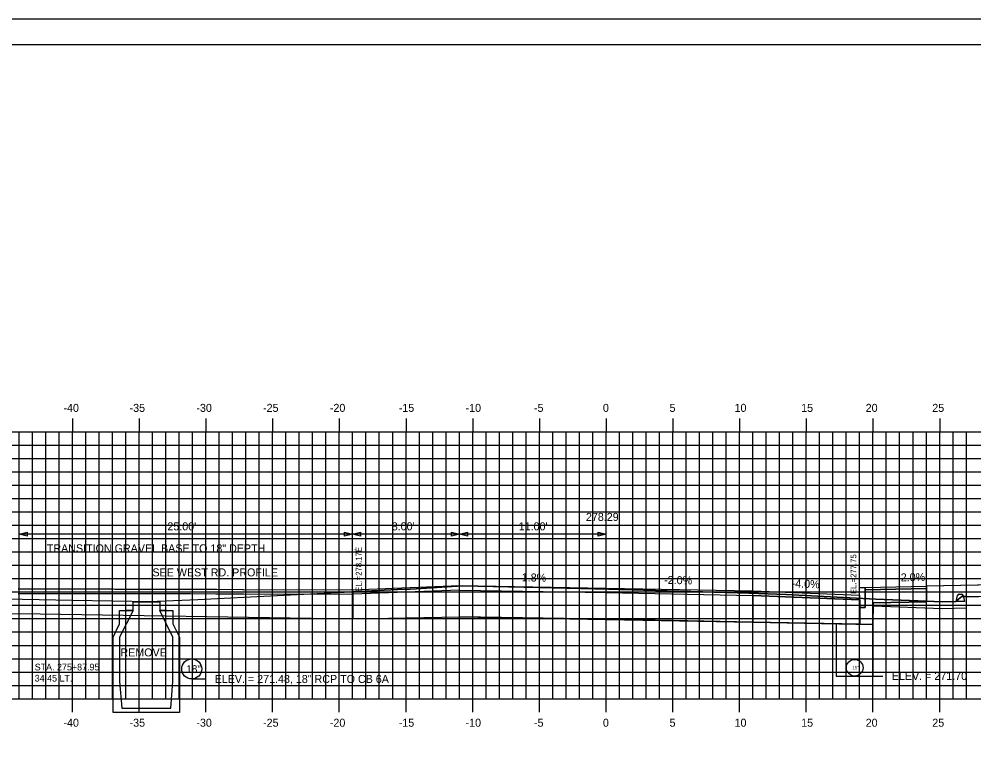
# Model space of a CAD drawing. Extents: x 853563 to 853733, y 366268 to 366378.
# Drawn here: x 853601.8 to 853673.3, y 366324.1 to 366378.2 of the extents above; entities that cross this region are included whole.
import ezdxf

# ---------------------------------------------------------------- set-up
doc = ezdxf.new("R2010")
doc.units = 0
for name, color, linetype in [('ANNOTATION', 7, 'Continuous'), ('BORDER', 7, 'Continuous'), ('D_Curb_Type_1_Rt', 7, 'Continuous'), ('D_Drainage_Culvert', 7, 'Continuous'), ('D_Roadway_Centerline_Text', 7, 'Continuous'), ('D_Roadway_Edge_Shoulder', 7, 'Continuous'), ('D_Roadway_Edge_TW', 7, 'Continuous'), ('D_Roadway_FinishedGrade', 7, 'Continuous'), ('D_Roadway_Sidewalks_Paved', 7, 'Continuous'), ('D_Roadway_SubGrade', 7, 'Continuous'), ('D_Text_Monospaced', 7, 'Continuous'), ('D_Text_Standard', 7, 'Continuous'), ('DIMENSIONS', 7, 'Continuous'), ('H_V ANNOTATION', 7, 'Continuous'), ('JUNK COM EXC', 7, 'Continuous'), ('JUNK FILL', 7, 'Continuous'), ('junk grubnfill', 7, 'Continuous'), ('junk strct exc', 7, 'Continuous'), ('MAJOR', 7, 'Continuous'), ('MINOR', 7, 'Continuous'), ('PDRAIN', 7, 'Continuous'), ('PLOT BOUNDARY', 7, 'Continuous'), ('S_Curb_Type_3', 7, 'Continuous'), ('S_Drainage_CB', 7, 'Continuous'), ('S_Roadway_Centerline', 7, 'Continuous')]:
    doc.layers.add(name, color=color, linetype=linetype)

msp = doc.modelspace()

# ---------------------------------------------------------------- linework, layer by layer
at = {"layer": 'BORDER'}
msp.add_line((853730.768, 366376.236), (853570.768, 366376.236), dxfattribs=at)
at = {"layer": 'D_Curb_Type_1_Rt'}
for points in [[(853665.184, 366335.573), (853665.184, 366334.073), (853664.767, 366334.073), (853664.767, 366335.573)], [(853665.184, 366335.573), (853665.184, 366334.073), (853664.768, 366334.073), (853664.768, 366335.573)]]:
    msp.add_lwpolyline(points, close=True, dxfattribs=at)
at = {"layer": 'D_Drainage_Culvert'}
msp.add_circle((853614.705, 366329.466), 0.75, dxfattribs=at)
at = {"layer": 'D_Roadway_Edge_Shoulder'}
msp.add_lwpolyline([(853656.768, 366335.31), (853664.768, 366334.99), (853664.768, 366334.656), (853656.768, 366334.976)], close=True, dxfattribs=at)
at = {"layer": 'D_Roadway_Edge_TW'}
msp.add_line((853626.768, 366335.393), (853626.771, 366335.06), dxfattribs=at)
for points in [[(853626.768, 366335.393), (853634.768, 366335.713), (853645.768, 366335.53), (853656.768, 366335.31), (853664.767, 366334.989)], [(853601.69, 366335.461), (853601.808, 366335.46), (853601.92, 366335.461), (853601.952, 366335.461), (853602.205, 366335.461), (853602.274, 366335.461), (853602.357, 366335.461), (853602.379, 366335.461), (853603.085, 366335.461), (853603.249, 366335.461), (853603.378, 366335.461), (853603.406, 366335.461), (853604.083, 366335.462), (853604.326, 366335.462), (853604.455, 366335.462), (853604.748, 366335.462), (853605.038, 366335.462), (853605.079, 366335.462), (853605.128, 366335.462), (853605.968, 366335.462), (853606.01, 366335.462), (853606.13, 366335.462), (853606.421, 366335.462), (853606.531, 366335.462), (853606.973, 366335.461), (853606.987, 366335.461), (853607.53, 366335.461), (853607.562, 366335.461), (853607.882, 366335.461), (853607.927, 366335.461), (853608.509, 366335.46), (853608.558, 366335.46), (853608.848, 366335.46), (853608.953, 366335.459), (853608.98, 366335.459), (853610.291, 366335.457), (853610.332, 366335.457), (853610.549, 366335.456), (853610.569, 366335.456), (853610.576, 366335.456), (853611.676, 366335.453), (853611.753, 366335.454), (853612.585, 366335.451), (853613.067, 366335.449), (853613.079, 366335.449), (853614.523, 366335.443), (853614.584, 366335.443), (853616.515, 366335.436), (853616.561, 366335.436), (853616.586, 366335.436), (853618.522, 366335.429), (853618.578, 366335.429), (853626.768, 366335.393)], [(853601.69, 366335.128), (853601.808, 366335.127), (853601.92, 366335.128), (853601.951, 366335.128), (853602.205, 366335.128), (853602.274, 366335.128), (853602.357, 366335.128), (853602.379, 366335.128), (853603.085, 366335.128), (853603.249, 366335.128), (853603.378, 366335.128), (853603.406, 366335.128), (853604.083, 366335.129), (853604.326, 366335.129), (853604.455, 366335.129), (853604.748, 366335.129), (853605.038, 366335.129), (853605.079, 366335.129), (853605.968, 366335.129), (853606.01, 366335.129), (853606.13, 366335.129), (853606.421, 366335.129), (853606.531, 366335.129), (853606.973, 366335.128), (853606.987, 366335.128), (853607.53, 366335.128), (853607.562, 366335.128), (853607.882, 366335.128), (853607.927, 366335.128), (853608.509, 366335.127), (853608.558, 366335.127), (853608.848, 366335.127), (853608.953, 366335.126), (853608.98, 366335.126), (853610.291, 366335.124), (853610.332, 366335.124), (853610.549, 366335.123), (853610.569, 366335.123), (853610.575, 366335.123), (853611.676, 366335.12), (853611.753, 366335.121), (853612.584, 366335.118), (853613.067, 366335.116), (853613.079, 366335.116), (853614.523, 366335.11), (853614.584, 366335.11), (853616.515, 366335.103), (853616.561, 366335.103), (853616.585, 366335.103), (853618.522, 366335.096), (853618.578, 366335.096), (853626.771, 366335.06)]]:
    msp.add_lwpolyline(points, dxfattribs=at)
at = {"layer": 'D_Roadway_FinishedGrade'}
msp.add_line((853685.017, 366335.97), (853669.773, 366335.664), dxfattribs=at)
at = {"layer": 'D_Roadway_Sidewalks_Paved'}
for points in [[(853665.184, 366335.573), (853669.773, 366335.665), (853669.773, 366335.498), (853665.184, 366335.406)], [(853665.184, 366335.572), (853669.773, 366335.664), (853669.773, 366335.497), (853665.184, 366335.406)]]:
    msp.add_lwpolyline(points, close=True, dxfattribs=at)
at = {"layer": 'D_Roadway_SubGrade'}
for p, q in [((853601.768, 366333.627), (853601.768, 366335.127)), ((853672.768, 366334.037), (853672.768, 366334.9))]:
    msp.add_line(p, q, dxfattribs=at)
for points in [[(853634.771, 366335.38), (853626.771, 366335.06), (853626.771, 366333.22), (853634.771, 366333.38)], [(853634.771, 366333.38), (853634.771, 366335.38), (853645.771, 366335.196), (853656.771, 366334.976), (853656.771, 366332.976), (853645.771, 366333.196)], [(853656.768, 366334.976), (853664.768, 366334.656), (853664.768, 366334.073), (853664.768, 366332.816), (853656.768, 366332.976)], [(853656.771, 366334.976), (853664.771, 366334.656), (853664.771, 366332.816), (853656.771, 366332.976)], [(853665.184, 366335.406), (853669.773, 366335.498), (853669.773, 366334.498), (853665.773, 366334.418), (853665.768, 366332.796), (853664.768, 366332.816), (853664.768, 366334.073), (853665.184, 366334.073)]]:
    msp.add_lwpolyline(points, close=True, dxfattribs=at)
for points in [[(853664.771, 366332.816), (853665.771, 366332.796), (853665.771, 366334.418), (853669.773, 366334.497), (853669.773, 366335.497)], [(853665.771, 366334.207), (853670.96, 366333.998), (853672.768, 366334.037)], [(853576.803, 366333.458), (853601.768, 366333.627), (853626.771, 366333.22)]]:
    msp.add_lwpolyline(points, dxfattribs=at)
at = {"layer": 'D_Text_Standard'}
for points in [[(853614.705, 366328.716), (853615.063, 366328.716), (853615.743, 366328.716)], [(853665.771, 366328.936), (853665.817, 366328.936), (853666.497, 366328.936)]]:
    msp.add_lwpolyline(points, dxfattribs=at)
at = {"layer": 'DIMENSIONS'}
for p, q in [((853601.768, 366335.845), (853601.768, 366339.957)), ((853626.768, 366335.593), (853626.768, 366339.957)), ((853626.768, 366336.884), (853626.768, 366339.957)), ((853634.768, 366335.913), (853634.768, 366339.957)), ((853645.768, 366335.73), (853645.768, 366339.957)), ((853626.768, 366339.557), (853601.768, 366339.557)), ((853634.768, 366339.557), (853626.768, 366339.557)), ((853645.768, 366339.557), (853634.768, 366339.557))]:
    msp.add_line(p, q, dxfattribs=at)
for points in [[(853602.368, 366339.407), (853601.768, 366339.557), (853602.368, 366339.707)], [(853626.168, 366339.707), (853626.768, 366339.557), (853626.168, 366339.407)], [(853627.368, 366339.407), (853626.768, 366339.557), (853627.368, 366339.707)], [(853634.168, 366339.707), (853634.768, 366339.557), (853634.168, 366339.407)], [(853635.368, 366339.407), (853634.768, 366339.557), (853635.368, 366339.707)], [(853645.168, 366339.707), (853645.768, 366339.557), (853645.168, 366339.407)]]:
    msp.add_lwpolyline(points, close=True, dxfattribs=at)
at = {"layer": 'JUNK COM EXC'}
msp.add_lwpolyline([(853626.768, 366335.249), (853626.771, 366333.22), (853634.771, 366333.38), (853656.771, 366332.976), (853665.771, 366332.796), (853665.771, 366334.418), (853669.773, 366334.497), (853669.773, 366334.546), (853665.98, 366334.699), (853662.578, 366334.881), (853659.261, 366335.059), (853656.49, 366335.136), (853645.97, 366335.444), (853640.757, 366335.567), (853635.009, 366335.685), (853631.517, 366335.478), (853631.077, 366335.457), (853630.126, 366335.415), (853626.768, 366335.249)], dxfattribs=at)
at = {"layer": 'JUNK FILL'}
msp.add_lwpolyline([(853669.768, 366335.664), (853669.768, 366335.497), (853669.773, 366335.497), (853669.773, 366334.546), (853669.775, 366334.546), (853670.965, 366334.498), (853671.996, 366334.52), (853672.426, 366334.897), (853672.831, 366334.9), (853673.692, 366334.906), (853676.746, 366334.989), (853679.799, 366335.073), (853681.402, 366335.295), (853683.005, 366335.518), (853685.081, 366335.984), (853677.395, 366335.817), (853669.773, 366335.664)], close=True, dxfattribs=at)
at = {"layer": 'junk grubnfill'}
msp.add_lwpolyline([(853669.773, 366334.546), (853669.773, 366334.497), (853665.771, 366334.418), (853665.771, 366334.207), (853670.96, 366333.998), (853672.768, 366334.037), (853672.768, 366334.9), (853672.426, 366334.897), (853672.062, 366334.59), (853671.996, 366334.52), (853670.965, 366334.498), (853669.773, 366334.546)], dxfattribs=at)
at = {"layer": 'junk strct exc'}
msp.add_lwpolyline([(853663.021, 366332.851), (853663.021, 366328.936), (853665.771, 366328.936), (853665.771, 366332.796)], close=True, dxfattribs=at)
at = {"layer": 'MAJOR'}
for p, q in [((853605.768, 366348.238), (853605.768, 366347.236)), ((853610.768, 366348.238), (853610.768, 366347.236)), ((853615.768, 366348.238), (853615.768, 366347.236)), ((853620.768, 366348.238), (853620.768, 366347.236)), ((853625.768, 366348.238), (853625.768, 366347.236)), ((853630.768, 366348.238), (853630.768, 366347.236)), ((853635.768, 366348.238), (853635.768, 366347.236)), ((853640.768, 366348.238), (853640.768, 366347.236)), ((853645.768, 366348.238), (853645.768, 366347.236)), ((853650.768, 366348.238), (853650.768, 366347.236)), ((853655.768, 366348.238), (853655.768, 366347.236)), ((853660.768, 366348.238), (853660.768, 366347.236)), ((853665.768, 366348.238), (853665.768, 366347.236)), ((853670.768, 366348.238), (853670.768, 366347.236)), ((853575.768, 366347.236), (853715.768, 366347.236)), ((853575.768, 366347.236), (853715.768, 366347.236)), ((853605.768, 366327.236), (853605.768, 366347.236)), ((853610.768, 366327.236), (853610.768, 366347.236)), ((853615.768, 366327.236), (853615.768, 366347.236)), ((853620.768, 366327.236), (853620.768, 366347.236)), ((853625.768, 366327.236), (853625.768, 366347.236)), ((853630.768, 366327.236), (853630.768, 366347.236)), ((853635.768, 366327.236), (853635.768, 366347.236)), ((853640.768, 366327.236), (853640.768, 366347.236)), ((853645.768, 366327.236), (853645.768, 366347.236)), ((853650.768, 366327.236), (853650.768, 366347.236)), ((853655.768, 366327.236), (853655.768, 366347.236)), ((853660.768, 366327.236), (853660.768, 366347.236)), ((853665.768, 366327.236), (853665.768, 366347.236)), ((853670.768, 366327.236), (853670.768, 366347.236)), ((853575.768, 366342.236), (853715.768, 366342.236)), ((853575.768, 366337.236), (853715.768, 366337.236)), ((853575.768, 366332.236), (853715.768, 366332.236)), ((853575.768, 366327.236), (853715.768, 366327.236)), ((853575.768, 366327.236), (853715.768, 366327.236)), ((853605.768, 366326.234), (853605.768, 366327.236)), ((853610.768, 366326.234), (853610.768, 366327.236)), ((853615.768, 366326.234), (853615.768, 366327.236)), ((853620.768, 366326.234), (853620.768, 366327.236)), ((853625.768, 366326.234), (853625.768, 366327.236)), ((853630.768, 366326.234), (853630.768, 366327.236)), ((853635.768, 366326.234), (853635.768, 366327.236)), ((853640.768, 366326.234), (853640.768, 366327.236)), ((853645.768, 366326.234), (853645.768, 366327.236)), ((853650.768, 366326.234), (853650.768, 366327.236)), ((853655.768, 366326.234), (853655.768, 366327.236)), ((853660.768, 366326.234), (853660.768, 366327.236)), ((853665.768, 366326.234), (853665.768, 366327.236)), ((853670.768, 366326.234), (853670.768, 366327.236))]:
    msp.add_line(p, q, dxfattribs=at)
at = {"layer": 'MINOR'}
for p, q in [((853601.768, 366327.236), (853601.768, 366347.236)), ((853602.768, 366327.236), (853602.768, 366347.236)), ((853603.768, 366327.236), (853603.768, 366347.236)), ((853604.768, 366327.236), (853604.768, 366347.236)), ((853606.768, 366327.236), (853606.768, 366347.236)), ((853607.768, 366327.236), (853607.768, 366347.236)), ((853608.768, 366327.236), (853608.768, 366347.236)), ((853609.768, 366327.236), (853609.768, 366347.236)), ((853611.768, 366327.236), (853611.768, 366347.236)), ((853612.768, 366327.236), (853612.768, 366347.236)), ((853613.768, 366327.236), (853613.768, 366347.236)), ((853614.768, 366327.236), (853614.768, 366347.236)), ((853616.768, 366327.236), (853616.768, 366347.236)), ((853617.768, 366327.236), (853617.768, 366347.236)), ((853618.768, 366327.236), (853618.768, 366347.236)), ((853619.768, 366327.236), (853619.768, 366347.236)), ((853621.768, 366327.236), (853621.768, 366347.236)), ((853622.768, 366327.236), (853622.768, 366347.236)), ((853623.768, 366327.236), (853623.768, 366347.236)), ((853624.768, 366327.236), (853624.768, 366347.236)), ((853626.768, 366327.236), (853626.768, 366347.236)), ((853627.768, 366327.236), (853627.768, 366347.236)), ((853628.768, 366327.236), (853628.768, 366347.236)), ((853629.768, 366327.236), (853629.768, 366347.236)), ((853631.768, 366327.236), (853631.768, 366347.236)), ((853632.768, 366327.236), (853632.768, 366347.236)), ((853633.768, 366327.236), (853633.768, 366347.236)), ((853634.768, 366327.236), (853634.768, 366347.236)), ((853636.768, 366327.236), (853636.768, 366347.236)), ((853637.768, 366327.236), (853637.768, 366347.236)), ((853638.768, 366327.236), (853638.768, 366347.236)), ((853639.768, 366327.236), (853639.768, 366347.236)), ((853641.768, 366327.236), (853641.768, 366347.236)), ((853642.768, 366327.236), (853642.768, 366347.236)), ((853643.768, 366327.236), (853643.768, 366347.236)), ((853644.768, 366327.236), (853644.768, 366347.236)), ((853646.768, 366327.236), (853646.768, 366347.236)), ((853647.768, 366327.236), (853647.768, 366347.236)), ((853648.768, 366327.236), (853648.768, 366347.236)), ((853649.768, 366327.236), (853649.768, 366347.236)), ((853651.768, 366327.236), (853651.768, 366347.236)), ((853652.768, 366327.236), (853652.768, 366347.236)), ((853653.768, 366327.236), (853653.768, 366347.236)), ((853654.768, 366327.236), (853654.768, 366347.236)), ((853656.768, 366327.236), (853656.768, 366347.236)), ((853657.768, 366327.236), (853657.768, 366347.236)), ((853658.768, 366327.236), (853658.768, 366347.236)), ((853659.768, 366327.236), (853659.768, 366347.236)), ((853661.768, 366327.236), (853661.768, 366347.236)), ((853662.768, 366327.236), (853662.768, 366347.236)), ((853663.768, 366327.236), (853663.768, 366347.236)), ((853664.768, 366327.236), (853664.768, 366347.236)), ((853666.768, 366327.236), (853666.768, 366347.236)), ((853667.768, 366327.236), (853667.768, 366347.236)), ((853668.768, 366327.236), (853668.768, 366347.236)), ((853669.768, 366327.236), (853669.768, 366347.236)), ((853671.768, 366327.236), (853671.768, 366347.236)), ((853672.768, 366327.236), (853672.768, 366347.236)), ((853575.768, 366346.236), (853715.768, 366346.236)), ((853575.768, 366345.236), (853715.768, 366345.236)), ((853575.768, 366344.236), (853715.768, 366344.236)), ((853575.768, 366343.236), (853715.768, 366343.236)), ((853575.768, 366341.236), (853715.768, 366341.236)), ((853575.768, 366340.236), (853715.768, 366340.236)), ((853575.768, 366339.236), (853715.768, 366339.236)), ((853575.768, 366338.236), (853715.768, 366338.236)), ((853575.768, 366336.236), (853715.768, 366336.236)), ((853575.768, 366335.236), (853715.768, 366335.236)), ((853575.768, 366334.236), (853715.768, 366334.236)), ((853575.768, 366333.236), (853715.768, 366333.236)), ((853575.768, 366331.236), (853715.768, 366331.236)), ((853575.768, 366330.236), (853715.768, 366330.236)), ((853575.768, 366329.236), (853715.768, 366329.236)), ((853575.768, 366328.236), (853715.768, 366328.236))]:
    msp.add_line(p, q, dxfattribs=at)
at = {"layer": 'PDRAIN'}
msp.add_lwpolyline([(853663.021, 366332.851), (853663.021, 366328.936), (853665.771, 366328.936), (853665.771, 366332.796)], dxfattribs=at)
msp.add_circle((853664.396, 366329.561), 0.625, dxfattribs=at)
at = {"layer": 'PLOT BOUNDARY'}
msp.add_lwpolyline([(853562.674, 366268.177), (853732.674, 366268.177), (853732.674, 366378.177), (853562.674, 366378.177)], close=True, dxfattribs=at)
at = {"layer": 'S_Curb_Type_3'}
for points in [[(853672.518, 366334.965), (853672.621, 366334.52), (853671.996, 366334.52), (853672.098, 366334.965)], [(853672.22, 366335.062), (853672.396, 366335.062)]]:
    msp.add_lwpolyline(points, dxfattribs=at)
for centre, start, end in [((853672.22, 366334.937), 90, 167.00538), ((853672.396, 366334.937), 12.99462, 90)]:
    msp.add_arc(centre, 0.125, start, end, dxfattribs=at)
at = {"layer": 'S_Drainage_CB'}
for p, q in [((853609.3, 366332.858), (853609.3, 366333.843)), ((853609.3, 366333.843), (853610.317, 366333.843)), ((853610.317, 366333.843), (853609.3, 366331.841)), ((853612.318, 366333.843), (853613.302, 366333.843)), ((853613.302, 366331.841), (853612.318, 366333.843)), ((853613.302, 366333.843), (853613.302, 366332.858)), ((853608.808, 366331.841), (853609.3, 366332.858)), ((853613.302, 366332.858), (853613.795, 366331.841)), ((853608.808, 366326.198), (853608.808, 366331.841)), ((853609.3, 366331.841), (853609.3, 366328.528)), ((853613.302, 366328.528), (853613.302, 366331.841)), ((853613.795, 366331.841), (853613.795, 366326.198)), ((853609.3, 366328.528), (853609.464, 366326.526)), ((853613.138, 366326.526), (853613.302, 366328.528)), ((853609.464, 366326.526), (853613.138, 366326.526)), ((853613.795, 366326.198), (853608.808, 366326.198))]:
    msp.add_line(p, q, dxfattribs=at)
msp.add_lwpolyline([(853609.825, 366333.884), (853610.317, 366333.884), (853610.317, 366334.508), (853612.318, 366334.508), (853612.318, 366333.884), (853612.81, 366333.884)], dxfattribs=at)
at = {"layer": 'S_Roadway_Centerline'}
msp.add_lwpolyline([(853590.768, 366334.911), (853605.767, 366334.615), (853611.714, 366334.524), (853611.768, 366334.524), (853611.809, 366334.524), (853611.898, 366334.526), (853612.008, 366334.531), (853612.064, 366334.534), (853612.146, 366334.539), (853615.174, 366334.667), (853619.112, 366334.87), (853630.126, 366335.415), (853631.077, 366335.457), (853631.517, 366335.478), (853635.009, 366335.685), (853640.757, 366335.567), (853645.97, 366335.444), (853656.49, 366335.136), (853659.261, 366335.059), (853662.578, 366334.881), (853665.98, 366334.699), (853670.965, 366334.498), (853671.996, 366334.52), (853672.062, 366334.59), (853672.426, 366334.897), (853673.692, 366334.906)], dxfattribs=at)

# ---------------------------------------------------------------- texts
at = {"layer": 'ANNOTATION'}
for s, p in [('TRANSITION GRAVEL BASE TO 18" DEPTH', (853603.846, 366338.207)), ('SEE WEST RD. PROFILE', (853611.764, 366336.404)), ('REMOVE', (853609.363, 366330.408))]:
    msp.add_text(s, height=0.6, dxfattribs=at).set_placement(p)
for s, rotation, p in [('1.8%', 359.04499, (853639.439, 366336.035)), ('-2.0%', 358.85424, (853650.111, 366335.843)), ('2.0%', 1.1478, (853667.855, 366336.026)), ('-4.0%', 357.70939, (853659.663, 366335.595)), ('-4.0%', 357.70925, (853659.663, 366335.594))]:
    msp.add_text(s, height=0.6, rotation=rotation, dxfattribs=at).set_placement(p)
at = {"layer": 'D_Roadway_Centerline_Text'}
msp.add_text('278.29', height=0.6, dxfattribs=at).set_placement((853644.253, 366340.562))
msp.add_text('278.29', height=0.6, dxfattribs=at).set_placement((853644.253, 366340.562))
at = {"layer": 'D_Text_Monospaced'}
for s, height, p in [('STA. 275+87.95', 0.49998, (853602.938, 366329.356)), ('34.45 LT.', 0.5, (853602.938, 366328.522))]:
    msp.add_text(s, height=height, dxfattribs=at).set_placement(p)
at = {"layer": 'D_Text_Standard'}
for s, p in [(' EL.=278.17È', (853627.437, 366335.078)), (' EL.=277.75', (853664.522, 366334.921))]:
    msp.add_text(s, height=0.4335, rotation=90, dxfattribs=at).set_placement(p)
for s, p in [('ELEV. = 271.70', (853667.177, 366328.636)), ('ELEV. = 271.48, 18" RCP TO CB 6A', (853616.423, 366328.416))]:
    msp.add_text(s, height=0.6, dxfattribs=at).set_placement(p)
at = {"layer": 'DIMENSIONS'}
for s, p in [("25.00'", (853612.884, 366339.857)), ("8.00'", (853629.7, 366339.857)), ("11.00'", (853639.216, 366339.857))]:
    msp.add_text(s, height=0.6, dxfattribs=at).set_placement(p)
at = {"layer": 'H_V ANNOTATION'}
for s, p in [('-40', (853605.093, 366348.736)), ('-35', (853610.048, 366348.736)), ('-30', (853615.056, 366348.736)), ('-25', (853620.053, 366348.736)), ('-20', (853625.061, 366348.736)), ('-15', (853630.224, 366348.736)), ('-10', (853635.232, 366348.736)), ('-5', (853640.358, 366348.736)), ('0', (853645.527, 366348.736)), ('5', (853650.519, 366348.736)), ('10', (853655.393, 366348.736)), ('15', (853660.385, 366348.736)), ('20', (853665.222, 366348.736)), ('25', (853670.213, 366348.736)), ('-40', (853605.093, 366325.136)), ('-35', (853610.048, 366325.136)), ('-30', (853615.056, 366325.136)), ('-25', (853620.053, 366325.136)), ('-20', (853625.061, 366325.136)), ('-15', (853630.224, 366325.136)), ('-10', (853635.232, 366325.136)), ('-5', (853640.358, 366325.136)), ('0', (853645.527, 366325.136)), ('5', (853650.519, 366325.136)), ('10', (853655.393, 366325.136)), ('15', (853660.385, 366325.136)), ('20', (853665.222, 366325.136)), ('25', (853670.213, 366325.136))]:
    msp.add_text(s, height=0.6, dxfattribs=at).set_placement(p)
at = {"layer": 'PDRAIN'}
for s, height, p in [('18"', 0.5625, (853614.293, 366329.185)), ('15"', 0.25, (853664.209, 366329.436))]:
    msp.add_text(s, height=height, dxfattribs=at).set_placement(p)
at = {"layer": 'S_Roadway_Centerline'}
for s, p in [('C', (853645.965, 366335.444)), ('C', (853645.965, 366335.444)), ('L', (853645.97, 366335.437)), ('L', (853645.97, 366335.437))]:
    msp.add_text(s, height=0.0146, dxfattribs=at).set_placement(p)

doc.saveas('drawing.dxf')
